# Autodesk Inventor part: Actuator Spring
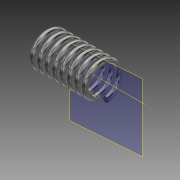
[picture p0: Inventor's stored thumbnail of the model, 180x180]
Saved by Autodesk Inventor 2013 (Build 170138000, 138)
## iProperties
Created: 2009-03
Part Number: Actuator Spring
Document SubType Name: Modeling
Designer: tangg
Density: 7.84 g/cm^3
Material: Steel, High Strength Low Alloy
Mass: 4.28111 g
Surface Area: 12.5295 cm^2
Volume: 0.54606 cm^3
Author: tangg
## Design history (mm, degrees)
sketch "Sketch1"
  geometry: 1 further point
sketch "3D Sketch1"
  node "Helical Curve1" dims "d0" = 19.4056, "d1" = 80, "d2" = 10, "d3" = 0
workplane "Work Plane1"
sketch "Sketch2"
  geometry: C1 r 0.875 at (0, 0); 1 further point
  constraints: 1 centre point
  dimensions: "d5" = 1.75 diameter of C1
sweep "Sweep1" sketch "Sketch2" dims "d4" = 0
body "Solid1"
